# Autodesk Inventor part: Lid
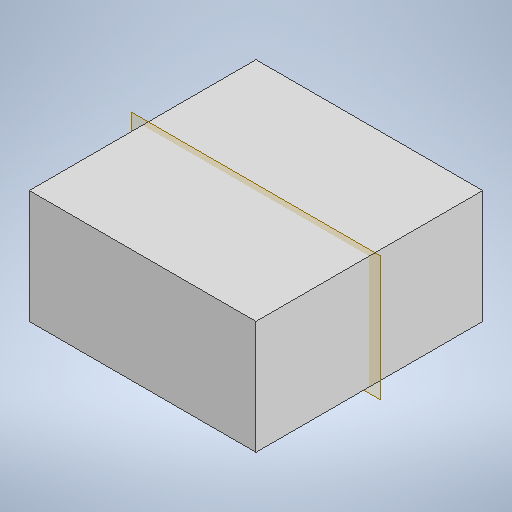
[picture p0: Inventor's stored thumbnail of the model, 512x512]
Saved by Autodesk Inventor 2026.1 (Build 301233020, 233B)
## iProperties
Created: 2026-11
Part Number: Lid
Material: Generic
Document SubType Name: Modeling
Designer: hp
Density: 1 g/cm^3
Appearance: Default
Author: hp
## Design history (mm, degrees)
sketch "Sketch1"
  geometry: L1 (-20, 20)-(20, 20); L2 (20, 20)-(20, -20); L3 (20, -20)-(-20, -20); L4 (-20, -20)-(-20, 20); L5 (-20, 20)-(20, -20); L6 (20, 20)-(-20, -20); 1 further point
  constraints: 12 end point, 2 midpoint, 2 parallel, 1 horizontal, 1 perpendicular
  dimensions: "d0" = 40 distance of L2.end L3.end; "d1" = 40 distance of L1.end L2.end
extrude "Extrusion1" new body sketch "Sketch1" distance "d2" = 20; taper "d3" = 0 deg
workplane "Work Plane1"
sketch "Sketch3"
  geometry: L1 (20, 0)-(20, 15.2); L2 (20, 15.2)-(38, 15.2); L3 (38, 15.2)-(38, 0); L4 (40, 0)-(0, 0) reference
  constraints: 6 end point, 1 horizontal, 1 perpendicular, 1 point on line, 1 vertical
  dimensions: "d8" = 15.2 distance of L1.start L1.end; "d9" = 18 distance of L1.end L2.end
revolve "Revolution2" sketch "Sketch3" stored, may be unused: angle "d10" = 360 deg
sketch "Sketch5"
  geometry: L1 (20, -20)-(-20, -20) reference; L2 (20, 20)-(20, -20) reference; L3 (-20, 20)-(20, 20) reference; L4 (-20, -20)-(-20, 20) reference; L5 (0, 20)-(0, -20); L6 (-20, 0)-(20, 0); C1 r 18 at (0, 0) reference; C2 r 2.55 at (-16, 16); C3 r 2.55 at (16, 16); C4 r 2.55 at (-16, -16); C5 r 2.55 at (16, -16); 1 further point
  constraints: 4 centre point, 4 end point, 4 midpoint, 3 symmetric about line, 3 other
  dimensions: "d14" = 5.1 diameter of C2; "d15" = 4 distance from line of L4 C2.centre (= d16); "d16" = 4 distance from line of L3 C2.centre
extrude "Extrusion3" cut sketch "Sketch5" distance "d17" = 2.2; taper "d18" = 0 deg
body "Solid1"
node "Projected Loop2"
